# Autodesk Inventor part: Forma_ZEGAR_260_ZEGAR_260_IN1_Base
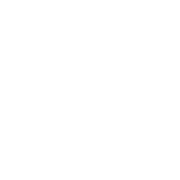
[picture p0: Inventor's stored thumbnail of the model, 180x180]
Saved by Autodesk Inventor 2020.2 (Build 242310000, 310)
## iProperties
Created: 2015-01
Part Number: Forma_ZEGAR_260_ZEGAR_260_IN1_Base
Material: Ogólny
Document SubType Name: Modeling
Designer: F.Stasiak
Density: 1 g/cm^3
Appearance: Domyślna
Catalog Web Link: www.expertbooks.pl
Manager: www.cadconsulting.pl
Company: Fabian Stasiak CAD Consulting
Author: F.Stasiak
Subject: Zbiór ćwiczeń. Autodesk Inventor 2020. Kurs Professional
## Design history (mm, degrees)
node "Forma_ZEGAR_260_ZEGAR_260_MP"
node "Bryła1"
